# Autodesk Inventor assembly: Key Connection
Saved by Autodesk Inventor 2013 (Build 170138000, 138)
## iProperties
Created: 2015-03
Part Number: Key Connection
Document SubType Name: Assembly
Designer: Uglješa
ClientObjectVersion: 1
Author: Uglješa
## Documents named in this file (2)
- C:\Users\Uglješa\Desktop\Assembly1\Design Accelerator\Key Connection2.iam
- C:\Users\Uglješa\Documents\Inventor\Content Center Files\R2013\en-US\ISO 2491 - A\ISO 2491 - A  18 x 7 x 50.ipt
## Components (1 placed, 1 different names)
1. ISO 2491 A A  18 x 7 x 50:1
